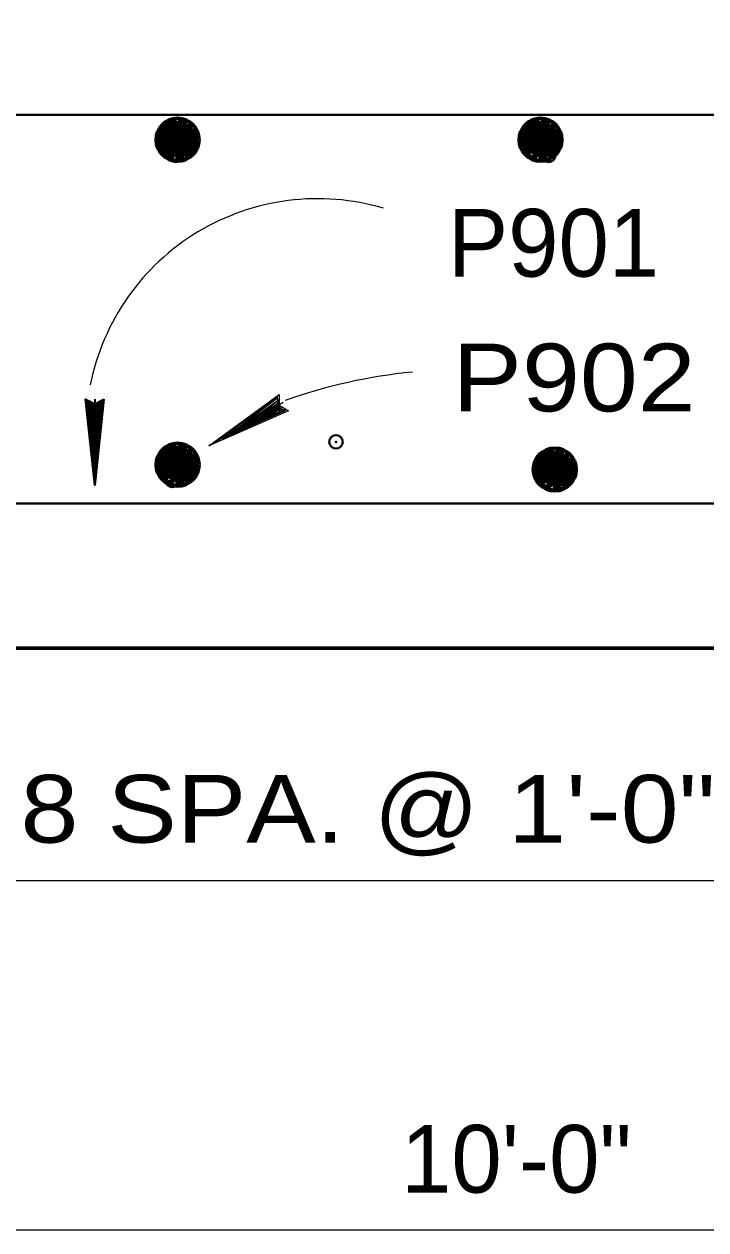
# Model space of a CAD drawing. Extents: x 14.14 to 17.34, y -1.61 to 0.38.
# Drawn here: x 16.1851 to 16.269, y -0.0868 to 0.0616 of the extents above; entities that cross this region are included whole.
import ezdxf

# ---------------------------------------------------------------- set-up
doc = ezdxf.new("R2010")
doc.units = 0
doc.header["$LTSCALE"] = 0.0033
doc.header["$PDMODE"] = 32
doc.header["$PDSIZE"] = 0.00165
doc.layers.add('1', color=7, linetype='Continuous', lineweight=40)

msp = doc.modelspace()

# ---------------------------------------------------------------- linework, layer by layer
at = {"layer": '1'}
for p, q in [((16.017333, 0.050417), (16.482, 0.050417)), ((16.202333, 0.04925), (16.206167, 0.048583)), ((16.20425, 0.048417), (16.205583, 0.049417)), ((16.206333, 0.048583), (16.205083, 0.04975)), ((16.247, 0.04925), (16.250833, 0.048583)), ((16.248917, 0.048417), (16.25025, 0.049417)), ((16.251, 0.048583), (16.24975, 0.04975)), ((16.201917, 0.048917), (16.2065, 0.04675)), ((16.202, 0.0475), (16.205833, 0.04675)), ((16.202083, 0.047917), (16.205917, 0.04725)), ((16.202083, 0.04775), (16.205917, 0.047)), ((16.202167, 0.0485), (16.206083, 0.04775)), ((16.202167, 0.048333), (16.206083, 0.047583)), ((16.202167, 0.048083), (16.206, 0.047333)), ((16.20225, 0.048917), (16.206167, 0.04825)), ((16.20225, 0.04875), (16.206167, 0.048)), ((16.246583, 0.048917), (16.251167, 0.04675)), ((16.246667, 0.0475), (16.2505, 0.04675)), ((16.24675, 0.047917), (16.250583, 0.04725)), ((16.24675, 0.04775), (16.250583, 0.047)), ((16.246833, 0.0485), (16.25075, 0.04775)), ((16.246833, 0.048333), (16.25075, 0.047583)), ((16.246833, 0.048083), (16.250667, 0.047333)), ((16.246917, 0.048917), (16.250833, 0.04825)), ((16.246917, 0.04875), (16.250833, 0.048)), ((16.20175, 0.046167), (16.205583, 0.045417)), ((16.201833, 0.046667), (16.20575, 0.045917)), ((16.201833, 0.0465), (16.205667, 0.04575)), ((16.201833, 0.04625), (16.205667, 0.045583)), ((16.201917, 0.047083), (16.205833, 0.046333)), ((16.202, 0.047333), (16.205833, 0.046583)), ((16.246417, 0.046167), (16.25025, 0.045417)), ((16.2465, 0.046667), (16.250417, 0.045917)), ((16.2465, 0.0465), (16.250333, 0.04575)), ((16.2465, 0.04625), (16.250333, 0.045583)), ((16.246583, 0.047083), (16.2505, 0.046333)), ((16.246667, 0.047333), (16.2505, 0.046583)), ((16.20175, 0.046), (16.205583, 0.04525)), ((16.206083, 0.04575), (16.202333, 0.045333)), ((16.246417, 0.046), (16.25025, 0.04525)), ((16.25075, 0.04575), (16.247, 0.045333)), ((16.201917, 0.008917), (16.2065, 0.00675)), ((16.20225, 0.008917), (16.206167, 0.00825)), ((16.202333, 0.00925), (16.206167, 0.008583)), ((16.20425, 0.008417), (16.205583, 0.009417)), ((16.206333, 0.008583), (16.205083, 0.00975)), ((16.25275, 0.008), (16.2515, 0.009167)), ((16.202, 0.0075), (16.205833, 0.00675)), ((16.202083, 0.007917), (16.205917, 0.00725)), ((16.202083, 0.00775), (16.205917, 0.007)), ((16.202167, 0.0085), (16.206083, 0.00775)), ((16.202167, 0.008333), (16.206083, 0.007583)), ((16.202167, 0.008083), (16.206, 0.007333)), ((16.20225, 0.00875), (16.206167, 0.008)), ((16.248333, 0.008333), (16.252917, 0.006167)), ((16.248583, 0.007917), (16.2525, 0.007167)), ((16.248583, 0.00775), (16.2525, 0.007)), ((16.248583, 0.0075), (16.252417, 0.00675)), ((16.248667, 0.008333), (16.252583, 0.007667)), ((16.248667, 0.008167), (16.252583, 0.007417)), ((16.24875, 0.008667), (16.252583, 0.008)), ((16.250667, 0.007833), (16.252, 0.008833)), ((16.20175, 0.006167), (16.205583, 0.005417)), ((16.20175, 0.006), (16.205583, 0.00525)), ((16.201833, 0.006667), (16.20575, 0.005917)), ((16.201833, 0.0065), (16.205667, 0.00575)), ((16.201833, 0.00625), (16.205667, 0.005583)), ((16.201917, 0.007083), (16.205833, 0.006333)), ((16.202, 0.007333), (16.205833, 0.006583)), ((16.24825, 0.006083), (16.252167, 0.005333)), ((16.248333, 0.0065), (16.25225, 0.00575)), ((16.248417, 0.006917), (16.25225, 0.006167)), ((16.248417, 0.00675), (16.25225, 0.006)), ((16.2485, 0.007333), (16.252333, 0.006667)), ((16.2485, 0.007167), (16.252333, 0.006417)), ((16.206083, 0.00575), (16.202333, 0.005333)), ((16.248167, 0.005583), (16.252, 0.004833)), ((16.248167, 0.005417), (16.252, 0.004667)), ((16.24825, 0.005917), (16.252083, 0.005167)), ((16.24825, 0.005667), (16.252083, 0.005)), ((16.2525, 0.005167), (16.24875, 0.00475)), ((16.01775, 0.002583), (16.481833, 0.002583))]:
    msp.add_line(p, q, dxfattribs=at)
at = {"layer": '1', "lineweight": 60}
for p, q in [((16.202167, 0.048917), (16.202, 0.046)), ((16.202417, 0.048917), (16.202167, 0.046)), ((16.202583, 0.048917), (16.202417, 0.045917)), ((16.20275, 0.048917), (16.2025, 0.045917)), ((16.202917, 0.048917), (16.20275, 0.045917)), ((16.203167, 0.048917), (16.203, 0.045917)), ((16.203417, 0.048917), (16.203167, 0.045917)), ((16.2035, 0.048833), (16.203333, 0.045917)), ((16.203667, 0.048833), (16.2035, 0.045917)), ((16.203833, 0.048833), (16.203667, 0.045917)), ((16.204083, 0.048833), (16.203833, 0.045917)), ((16.20425, 0.048833), (16.204083, 0.045917)), ((16.2045, 0.04875), (16.20425, 0.045833)), ((16.20475, 0.04875), (16.2045, 0.045833)), ((16.204917, 0.04875), (16.20475, 0.045833)), ((16.205, 0.04875), (16.204833, 0.045833)), ((16.205167, 0.04875), (16.205, 0.045833)), ((16.20525, 0.04875), (16.205083, 0.045833)), ((16.2055, 0.048667), (16.20525, 0.04575)), ((16.205667, 0.048667), (16.2055, 0.04575)), ((16.205833, 0.048667), (16.205583, 0.04575)), ((16.206, 0.048667), (16.205833, 0.04575)), ((16.20625, 0.048667), (16.206083, 0.04575)), ((16.2065, 0.04675), (16.206333, 0.048583)), ((16.246833, 0.048917), (16.246667, 0.046)), ((16.247083, 0.048917), (16.246833, 0.046)), ((16.24725, 0.048917), (16.247083, 0.045917)), ((16.247417, 0.048917), (16.247167, 0.045917)), ((16.247583, 0.048917), (16.247417, 0.045917)), ((16.247833, 0.048917), (16.247667, 0.045917)), ((16.248083, 0.048917), (16.247833, 0.045917)), ((16.248167, 0.048833), (16.248, 0.045917)), ((16.248333, 0.048833), (16.248167, 0.045917)), ((16.2485, 0.048833), (16.248333, 0.045917)), ((16.24875, 0.048833), (16.2485, 0.045917)), ((16.248917, 0.048833), (16.24875, 0.045917)), ((16.249167, 0.04875), (16.248917, 0.045833)), ((16.249417, 0.04875), (16.249167, 0.045833)), ((16.249583, 0.04875), (16.249417, 0.045833)), ((16.249667, 0.04875), (16.2495, 0.045833)), ((16.249833, 0.04875), (16.249667, 0.045833)), ((16.249917, 0.04875), (16.24975, 0.045833)), ((16.250167, 0.048667), (16.249917, 0.04575)), ((16.250333, 0.048667), (16.250167, 0.04575)), ((16.2505, 0.048667), (16.25025, 0.04575)), ((16.250667, 0.048667), (16.2505, 0.04575)), ((16.250917, 0.048667), (16.25075, 0.04575)), ((16.251167, 0.04675), (16.251, 0.048583)), ((16.2065, 0.04675), (16.20175, 0.046)), ((16.251167, 0.04675), (16.246417, 0.046)), ((16.202167, 0.008917), (16.202, 0.006)), ((16.202417, 0.008917), (16.202167, 0.006)), ((16.202583, 0.008917), (16.202417, 0.005917)), ((16.20275, 0.008917), (16.2025, 0.005917)), ((16.202917, 0.008917), (16.20275, 0.005917)), ((16.203167, 0.008917), (16.203, 0.005917)), ((16.203417, 0.008917), (16.203167, 0.005917)), ((16.2035, 0.008833), (16.203333, 0.005917)), ((16.203667, 0.008833), (16.2035, 0.005917)), ((16.203833, 0.008833), (16.203667, 0.005917)), ((16.204083, 0.008833), (16.203833, 0.005917)), ((16.20425, 0.008833), (16.204083, 0.005917)), ((16.2045, 0.00875), (16.20425, 0.005833)), ((16.20475, 0.00875), (16.2045, 0.005833)), ((16.204917, 0.00875), (16.20475, 0.005833)), ((16.205, 0.00875), (16.204833, 0.005833)), ((16.205167, 0.00875), (16.205, 0.005833)), ((16.20525, 0.00875), (16.205083, 0.005833)), ((16.2055, 0.008667), (16.20525, 0.00575)), ((16.205667, 0.008667), (16.2055, 0.00575)), ((16.205833, 0.008667), (16.205583, 0.00575)), ((16.206, 0.008667), (16.205833, 0.00575)), ((16.20625, 0.008667), (16.206083, 0.00575)), ((16.2065, 0.00675), (16.206333, 0.008583)), ((16.248583, 0.008333), (16.248417, 0.005417)), ((16.248833, 0.008333), (16.248583, 0.005417)), ((16.249, 0.008333), (16.248833, 0.005333)), ((16.249167, 0.008333), (16.248917, 0.005333)), ((16.249333, 0.008333), (16.249167, 0.005333)), ((16.249583, 0.008333), (16.249417, 0.005333)), ((16.249833, 0.008333), (16.249583, 0.005333)), ((16.249917, 0.00825), (16.24975, 0.005333)), ((16.250083, 0.00825), (16.249917, 0.005333)), ((16.25025, 0.00825), (16.250083, 0.005333)), ((16.2505, 0.00825), (16.25025, 0.005333)), ((16.250667, 0.00825), (16.2505, 0.005333)), ((16.250917, 0.008167), (16.250667, 0.00525)), ((16.251167, 0.008167), (16.250917, 0.00525)), ((16.251333, 0.008167), (16.251167, 0.00525)), ((16.251417, 0.008167), (16.25125, 0.00525)), ((16.251583, 0.008167), (16.251417, 0.00525)), ((16.251667, 0.008167), (16.2515, 0.00525)), ((16.251917, 0.008083), (16.251667, 0.005167)), ((16.252083, 0.008083), (16.251917, 0.005167)), ((16.25225, 0.008083), (16.252, 0.005167)), ((16.252417, 0.008083), (16.25225, 0.005167)), ((16.252667, 0.008083), (16.2525, 0.005167)), ((16.252917, 0.006167), (16.25275, 0.008)), ((16.2065, 0.00675), (16.20175, 0.006)), ((16.252917, 0.006167), (16.248167, 0.005417))]:
    msp.add_line(p, q, dxfattribs=at)
at = {"layer": '1', "lineweight": 35}
for p, q in [((16.19275, 0.015167), (16.193583, 0.007833)), ((16.192917, 0.015167), (16.193667, 0.007833)), ((16.193, 0.015167), (16.193833, 0.007833)), ((16.193167, 0.01525), (16.193917, 0.007917)), ((16.194667, 0.015167), (16.193667, 0.007333)), ((16.193833, 0.015417), (16.193833, 0.004833)), ((16.194667, 0.015167), (16.193833, 0.007333)), ((16.194833, 0.015167), (16.193917, 0.007333)), ((16.194833, 0.015167), (16.193917, 0.007333)), ((16.19475, 0.015167), (16.193917, 0.007333))]:
    msp.add_line(p, q, dxfattribs=at)
at = {"layer": '1', "lineweight": 13}
for p, q in [((16.217, 0.015), (16.207833, 0.009667)), ((16.21625, 0.01575), (16.210333, 0.011417)), ((16.216333, 0.015667), (16.210333, 0.011333)), ((16.216333, 0.015583), (16.2105, 0.011167)), ((16.216583, 0.015417), (16.2105, 0.011083)), ((16.21725, 0.014167), (16.21, 0.011083)), ((16.21725, 0.014167), (16.210083, 0.010917)), ((16.21725, 0.014083), (16.210083, 0.010833)), ((16.21725, 0.014), (16.210083, 0.010833)), ((16.21725, 0.014), (16.210083, 0.010833)), ((16.01775, -0.043833), (16.481833, -0.043833)), ((15.999583, -0.086833), (16.498917, -0.086833))]:
    msp.add_line(p, q, dxfattribs=at)
at = {"layer": '1', "lineweight": 60}
for points in [[(15.999667, -0.01525), (16.499667, -0.01525), (16.499667, 0.068083)], [(16.205583, 0.04525), (16.205583, 0.049417), (16.203917, 0.04475), (16.204417, 0.049917), (16.202333, 0.045333), (16.203083, 0.049833), (16.204667, 0.044833), (16.2015, 0.048167), (16.206333, 0.048583), (16.203083, 0.044917), (16.205083, 0.04975), (16.201917, 0.048917), (16.20175, 0.046)], [(16.202333, 0.045333), (16.203833, 0.047583), (16.201667, 0.0485), (16.203667, 0.049917), (16.203833, 0.047667), (16.2055, 0.045333), (16.2015, 0.047667), (16.20425, 0.048417)], [(16.205083, 0.04975), (16.203833, 0.047583), (16.206083, 0.04575)], [(16.25025, 0.04525), (16.25025, 0.049417), (16.248583, 0.04475), (16.249083, 0.049917), (16.247, 0.045333), (16.24775, 0.049833), (16.249333, 0.044833), (16.246167, 0.048167), (16.251, 0.048583), (16.24775, 0.044917), (16.24975, 0.04975), (16.246583, 0.048917), (16.246417, 0.046)], [(16.247, 0.045333), (16.2485, 0.047583), (16.246333, 0.0485), (16.248333, 0.049917), (16.2485, 0.047667), (16.250167, 0.045333), (16.246167, 0.047667), (16.248917, 0.048417)], [(16.24975, 0.04975), (16.2485, 0.047583), (16.25075, 0.04575)], [(16.201333, 0.04725), (16.2065, 0.047917), (16.201917, 0.048917)], [(16.246, 0.04725), (16.251167, 0.047917), (16.246583, 0.048917)], [(16.201333, 0.00725), (16.2065, 0.007917), (16.201917, 0.008917)], [(16.205583, 0.00525), (16.205583, 0.009417), (16.203917, 0.00475), (16.204417, 0.009917), (16.202333, 0.005333), (16.203083, 0.009833), (16.204667, 0.004833), (16.2015, 0.008167), (16.206333, 0.008583), (16.203083, 0.004917), (16.205083, 0.00975), (16.201917, 0.008917), (16.20175, 0.006)], [(16.202333, 0.005333), (16.203833, 0.007583), (16.201667, 0.0085), (16.203667, 0.009917), (16.203833, 0.007667), (16.2055, 0.005333), (16.2015, 0.007667), (16.20425, 0.008417)], [(16.205083, 0.00975), (16.203833, 0.007583), (16.206083, 0.00575)], [(16.252, 0.004667), (16.252, 0.008833), (16.250333, 0.004167), (16.250833, 0.009333), (16.24875, 0.00475), (16.2495, 0.00925), (16.251083, 0.00425), (16.247917, 0.007583), (16.25275, 0.008), (16.2495, 0.004333), (16.2515, 0.009167), (16.248333, 0.008333), (16.248167, 0.005417)], [(16.24875, 0.00475), (16.25025, 0.007), (16.248083, 0.007917), (16.250083, 0.009333), (16.25025, 0.007083), (16.251917, 0.00475), (16.247917, 0.007083), (16.250667, 0.007833)], [(16.2515, 0.009167), (16.25025, 0.007), (16.2525, 0.005167)], [(16.24775, 0.006667), (16.252917, 0.007333), (16.248333, 0.008333)]]:
    msp.add_lwpolyline(points, dxfattribs=at)
at = {"layer": '1'}
for points in [[(16.20175, 0.046), (16.203833, 0.04475), (16.205583, 0.04525), (16.2065, 0.04675)], [(16.246417, 0.046), (16.2485, 0.04475), (16.25025, 0.04525), (16.251167, 0.04675)], [(16.20175, 0.006), (16.203833, 0.00475), (16.205583, 0.00525), (16.2065, 0.00675)], [(16.248167, 0.005417), (16.25025, 0.004167), (16.252, 0.004667), (16.252917, 0.006167)]]:
    msp.add_lwpolyline(points, dxfattribs=at)
at = {"layer": '1', "lineweight": 35}
for points in [[(16.194917, 0.015417), (16.193833, 0.004833), (16.192667, 0.015417), (16.193833, 0.014833)], [(16.193917, 0.014667), (16.194, 0.01), (16.193917, 0.01), (16.193917, 0.010917), (16.194, 0.014667), (16.194083, 0.011667), (16.194167, 0.014833), (16.19425, 0.012583), (16.194333, 0.014833), (16.194083, 0.011333), (16.193917, 0.006667), (16.193667, 0.007583), (16.193667, 0.006333), (16.193667, 0.014667), (16.1935, 0.01225), (16.1935, 0.014833), (16.193917, 0.0095), (16.19325, 0.014833)]]:
    msp.add_lwpolyline(points, close=True, dxfattribs=at)
msp.add_lwpolyline([(16.193917, 0.014667), (16.194667, 0.015083), (16.194417, 0.014833), (16.194083, 0.014667), (16.194167, 0.014417), (16.1945, 0.014583), (16.19375, 0.01475), (16.19325, 0.014917), (16.192833, 0.015167)], dxfattribs=at)
at = {"layer": '1', "lineweight": 13}
for points in [[(16.217667, 0.014), (16.207833, 0.009667), (16.2165, 0.016), (16.2165, 0.014667)], [(16.216417, 0.0145), (16.212417, 0.012083), (16.212333, 0.012167), (16.213167, 0.012667), (16.2165, 0.014417), (16.213833, 0.012917), (16.216667, 0.014417), (16.214833, 0.013167), (16.216833, 0.01425), (16.213583, 0.012667), (16.2095, 0.0105), (16.21025, 0.01125), (16.209083, 0.010583), (16.216333, 0.014667), (16.214167, 0.013667), (16.216417, 0.014917), (16.211917, 0.011917), (16.21625, 0.015167)]]:
    msp.add_lwpolyline(points, close=True, dxfattribs=at)
msp.add_lwpolyline([(16.216417, 0.0145), (16.217167, 0.014), (16.21675, 0.014167), (16.2165, 0.014333), (16.216333, 0.01425), (16.216667, 0.013917), (16.216417, 0.01475), (16.216333, 0.01525), (16.21625, 0.01575)], dxfattribs=at)
at = {"layer": '1', "lineweight": 60}
for centre in [(16.204, 0.04735), (16.248667, 0.04735), (16.204, 0.00735), (16.250417, 0.006767)]:
    msp.add_circle(centre, 0.00264, dxfattribs=at)
at = {"layer": '1', "lineweight": 13}
for centre, radius, start, end in [((16.221216, 0.011576), 0.02852, 73.46463, 168.69611), ((16.239126, -0.045858), 0.064905, 95.48975, 109.69691)]:
    msp.add_arc(centre, radius, start, end, dxfattribs=at)
at = {"layer": '1'}
for p in [(16.20375, 0.045417), (16.249667, 0.045417), (16.2235, 0.010167), (16.203333, 0.005417), (16.249083, 0.005417)]:
    msp.add_point(p, dxfattribs=at)

# ---------------------------------------------------------------- texts
for s, height, p in [('P901', 0.008334, (16.23725, 0.0305)), ('10\'-0"', 0.008333, (16.2315, -0.08225))]:
    msp.add_text(s, height=height, dxfattribs=at).set_placement(p)
at = {"layer": '1', "width": 1.15}
for s, p in [('P902', (16.237833, 0.013917)), ('8 SPA. @ 1\'-0" C/C', (16.184667, -0.039167))]:
    msp.add_text(s, height=0.008334, dxfattribs=at).set_placement(p)

doc.saveas('drawing.dxf')
